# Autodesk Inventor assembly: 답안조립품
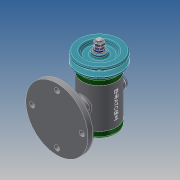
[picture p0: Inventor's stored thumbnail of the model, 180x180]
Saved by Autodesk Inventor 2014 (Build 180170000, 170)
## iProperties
Created: 2018-12
Part Number: 답안조립품
Document SubType Name: Assembly
Designer: kb542-13
Author: kb542-13
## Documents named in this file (15)
- C:\Users\kb542-13\Desktop\481207V1023\답안조립품.iam
- C:\Users\kb542-13\Desktop\481207V1023\본체.ipt
- C:\Users\kb542-13\Desktop\481207V1023\축.ipt
- C:\Users\kb542-13\Desktop\481207V1023\키 3 x 3 x 12.ipt
- C:\Users\kb542-13\Desktop\481207V1023\베어링 15 x 32 x 9.ipt
- C:\Users\kb542-13\Desktop\481207V1023\고무캡.ipt
- C:\Users\kb542-13\Desktop\481207V1023\V벨트풀리.ipt
- C:\Users\kb542-13\Desktop\481207V1023\와셔 8x17.ipt
- C:\Users\kb542-13\Desktop\481207V1023\스프링와셔 8.ipt
- C:\Users\kb542-13\Desktop\481207V1023\너트 M8.ipt
- 너트 M8.ipt
- C:\Users\kb542-13\Desktop\481207V1023\뒤커버.ipt
- C:\Users\kb542-13\Desktop\481207V1023\앞커버.ipt
- C:\Users\kb542-13\Desktop\481207V1023\오일 실 15 25 7.ipt
- C:\Users\kb542-13\Desktop\481207V1023\볼트 M4 x 12.ipt
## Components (2 placed, 2 different names)
1. 고무캡:1
2. V벨트풀리:1
